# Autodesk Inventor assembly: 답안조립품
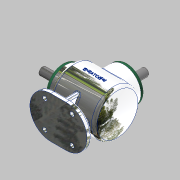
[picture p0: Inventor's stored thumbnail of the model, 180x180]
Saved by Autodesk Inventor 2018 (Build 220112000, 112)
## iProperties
Created: 2023-01
Part Number: 답안조립품
Material: 일반
Document SubType Name: Assembly
Designer: home
Author: home
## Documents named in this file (14)
- C:\Users\home\Desktop\730106V1007\답안조립품.iam
- C:\Users\home\Desktop\730106V1007\본체.ipt
- C:\Users\home\Desktop\730106V1007\커버.ipt
- C:\Users\home\Desktop\730106V1007\베어링 6203.ipt
- C:\Users\home\Desktop\730106V1007\메인 축.ipt
- 메인 축.ipt
- C:\Users\home\Desktop\730106V1007\서브 축.ipt
- 서브 축.ipt
- C:\Users\home\Desktop\730106V1007\메인 베벨기어.ipt
- C:\Users\home\Desktop\730106V1007\키 5x5.ipt
- C:\Users\home\Desktop\730106V1007\서브 베벨기어.ipt
- C:\Users\home\Desktop\730106V1007\키 4x4.ipt
- C:\Users\home\Desktop\730106V1007\오일실 17 32 8.ipt
- C:\Users\home\Desktop\730106V1007\M4.ipt
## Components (8 placed, 1 different names)
1. M4:1
2. M4:3
3. M4:4
4. M4:5
5. M4:2
6. M4:6
7. M4:7
8. M4:8
